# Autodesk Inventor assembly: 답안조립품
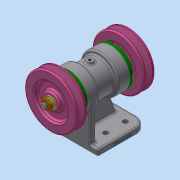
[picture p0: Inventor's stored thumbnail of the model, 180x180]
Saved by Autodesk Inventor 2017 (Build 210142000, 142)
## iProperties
Part Number: 답안조립품
Material: 일반
Document SubType Name: Assembly
Designer: mrc
Author: mrc
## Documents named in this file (12)
- C:\Users\mrc\Desktop\700606V1011\답안조립품.iam
- C:\Users\mrc\Desktop\700606V1011\본체.ipt
- C:\Users\mrc\Desktop\700606V1011\V-벨트풀리.ipt
- C:\Users\mrc\Desktop\700606V1011\너트 M10.ipt
- C:\Users\mrc\Desktop\700606V1011\베어링 6204.ipt
- C:\Users\mrc\Desktop\700606V1011\볼트 M4.ipt
- C:\Users\mrc\Desktop\700606V1011\스프링 와셔 10.ipt
- C:\Users\mrc\Desktop\700606V1011\오일 실 20 32 5.ipt
- C:\Users\mrc\Desktop\700606V1011\축.ipt
- C:\Users\mrc\Desktop\700606V1011\커버.ipt
- C:\Users\mrc\Desktop\700606V1011\키 5x5x12.ipt
- C:\Users\mrc\Desktop\700606V1011\평면 와셔 10x21.ipt
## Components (2 placed, 1 different names)
1. V-벨트풀리:1
2. V-벨트풀리:2
